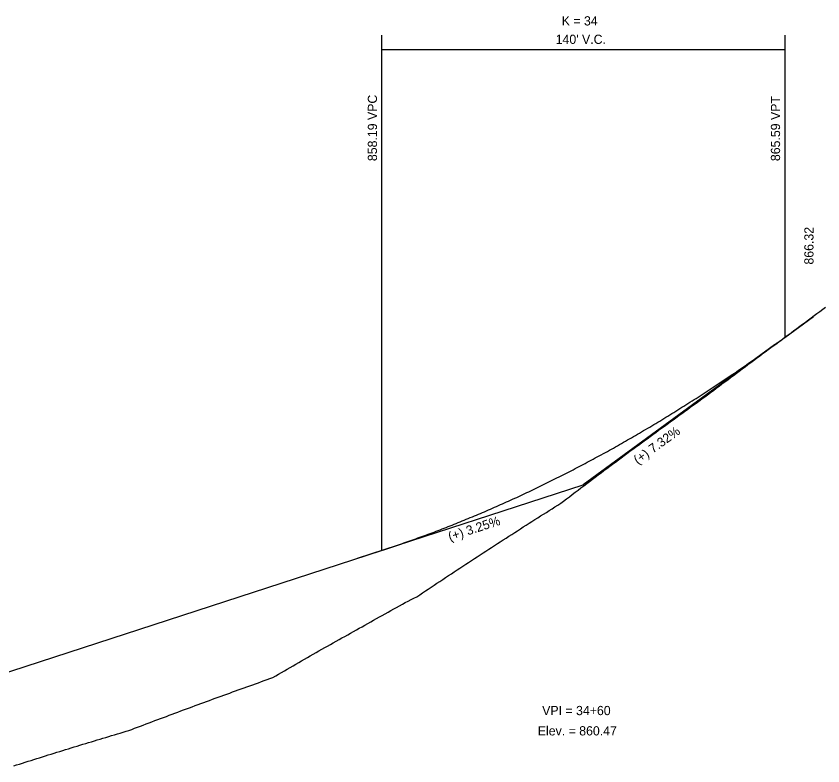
# Model space of a CAD drawing. Extents: x 1738393 to 1742179, y 1214897 to 1219897.
# Drawn here: x 1740142.4 to 1740422.6, y 1217903.8 to 1218164.3 of the extents above; entities that cross this region are included whole.
import ezdxf

# ---------------------------------------------------------------- set-up
doc = ezdxf.new("R2010")
doc.units = 0
for name, color, linetype in [('RD_DDB_GradeTX', 7, 'Continuous'), ('RD_DDB_Profile_EX', 7, 'Continuous'), ('RD_DDB_Profile_Lbl', 7, 'Continuous'), ('RD_DDB_Profile_PR', 7, 'Continuous'), ('RD_DDB_StripGrade', 7, 'Continuous'), ('RD_DDB_VCLbl', 7, 'Continuous')]:
    doc.layers.add(name, color=color, linetype=linetype)

msp = doc.modelspace()

# ---------------------------------------------------------------- linework, layer by layer
at = {"layer": 'RD_DDB_GradeTX'}
for p in [(1740405.87, 1218050.08), (1740261.02, 1217975.92)]:
    msp.add_line(p, (1740339.37, 1218001.42), dxfattribs=at)
at = {"layer": 'RD_DDB_Profile_EX'}
for points in [[(1740384.58, 1218034.23), (1740385.58, 1218034.98), (1740386.58, 1218035.73), (1740387.58, 1218036.48), (1740388.58, 1218037.22), (1740389.58, 1218037.97), (1740390.58, 1218038.72), (1740391.58, 1218039.47), (1740392.58, 1218040.21), (1740393.58, 1218040.96), (1740394.58, 1218041.71), (1740395.58, 1218042.45), (1740396.58, 1218043.2), (1740397.58, 1218043.94), (1740398.58, 1218044.69), (1740399.58, 1218045.43), (1740400.58, 1218046.18), (1740401.58, 1218046.92), (1740402.58, 1218047.67), (1740403.58, 1218048.41), (1740404.58, 1218049.16), (1740405.58, 1218049.87), (1740406.58, 1218050.58), (1740407.58, 1218051.32), (1740408.58, 1218052.07), (1740409.58, 1218052.81), (1740410.58, 1218053.55), (1740411.58, 1218054.29), (1740412.58, 1218055.03), (1740413.58, 1218055.78), (1740414.58, 1218056.52), (1740415.58, 1218057.26), (1740416.58, 1218058), (1740417.58, 1218058.74), (1740418.58, 1218059.49), (1740419.58, 1218060.23), (1740420.58, 1218060.97), (1740421.58, 1218061.71), (1740422.58, 1218062.45), (1740423.58, 1218063.19)], [(1740284.58, 1217964.57), (1740285.58, 1217965.24), (1740286.58, 1217965.91), (1740287.58, 1217966.57), (1740288.58, 1217967.24), (1740289.58, 1217967.9), (1740290.58, 1217968.56), (1740291.58, 1217969.23), (1740292.58, 1217969.89), (1740293.58, 1217970.55), (1740294.58, 1217971.21), (1740295.58, 1217971.87), (1740296.58, 1217972.53), (1740297.58, 1217973.18), (1740298.58, 1217973.84), (1740299.58, 1217974.5), (1740300.58, 1217975.15), (1740301.58, 1217975.81), (1740302.58, 1217976.46), (1740303.58, 1217977.11), (1740304.58, 1217977.76), (1740305.58, 1217978.41), (1740306.58, 1217979.06), (1740307.58, 1217979.71), (1740308.58, 1217980.36), (1740309.58, 1217981.01), (1740310.58, 1217981.65), (1740311.58, 1217982.3), (1740312.58, 1217982.94), (1740313.58, 1217983.59), (1740314.58, 1217984.23), (1740315.58, 1217984.87), (1740316.58, 1217985.51), (1740317.58, 1217986.15), (1740318.58, 1217986.79), (1740319.58, 1217987.43), (1740320.58, 1217988.07), (1740321.58, 1217988.71), (1740322.58, 1217989.35), (1740323.58, 1217989.98), (1740324.58, 1217990.62), (1740325.58, 1217991.25), (1740326.58, 1217991.88), (1740327.58, 1217992.51), (1740328.58, 1217993.15), (1740329.58, 1217993.78), (1740330.58, 1217994.4), (1740331.58, 1217995.03), (1740332.58, 1217995.79), (1740333.58, 1217996.56), (1740334.58, 1217997.32), (1740335.58, 1217998.08), (1740336.58, 1217998.84), (1740337.58, 1217999.59), (1740338.58, 1218000.35), (1740339.58, 1218001.11), (1740340.58, 1218001.87), (1740341.58, 1218002.62), (1740342.58, 1218003.37), (1740343.58, 1218004.13), (1740344.58, 1218004.88), (1740345.58, 1218005.63), (1740346.58, 1218006.38), (1740347.58, 1218007.13), (1740348.58, 1218007.88), (1740349.58, 1218008.63), (1740350.58, 1218009.37), (1740351.58, 1218010.12), (1740352.58, 1218010.87), (1740353.58, 1218011.61), (1740354.58, 1218012.35), (1740355.58, 1218013.08), (1740356.58, 1218013.81), (1740357.58, 1218014.54), (1740358.58, 1218015.27), (1740359.58, 1218016.01), (1740360.58, 1218016.74), (1740361.58, 1218017.47), (1740362.58, 1218018.2), (1740363.58, 1218018.93), (1740364.58, 1218019.66), (1740365.58, 1218020.39), (1740366.58, 1218021.12), (1740367.58, 1218021.85), (1740368.58, 1218022.57), (1740369.58, 1218023.3), (1740370.58, 1218024.03), (1740371.58, 1218024.76), (1740372.58, 1218025.48), (1740373.58, 1218026.21), (1740374.58, 1218026.94), (1740375.58, 1218027.66), (1740376.58, 1218028.39), (1740377.58, 1218029.11), (1740378.58, 1218029.84), (1740379.58, 1218030.56), (1740380.58, 1218031.28), (1740381.58, 1218031.99), (1740382.58, 1218032.74), (1740383.58, 1218033.49), (1740384.58, 1218034.23)], [(1740184.58, 1217917.24), (1740185.58, 1217917.61), (1740186.58, 1217917.99), (1740187.58, 1217918.37), (1740188.58, 1217918.75), (1740189.58, 1217919.12), (1740190.58, 1217919.5), (1740191.58, 1217919.87), (1740192.58, 1217920.25), (1740193.58, 1217920.62), (1740194.58, 1217921), (1740195.58, 1217921.37), (1740196.58, 1217921.74), (1740197.58, 1217922.12), (1740198.58, 1217922.49), (1740199.58, 1217922.86), (1740200.58, 1217923.23), (1740201.58, 1217923.6), (1740202.58, 1217923.97), (1740203.58, 1217924.34), (1740204.58, 1217924.71), (1740205.58, 1217925.07), (1740206.58, 1217925.44), (1740207.58, 1217925.82), (1740208.58, 1217926.18), (1740209.58, 1217926.55), (1740210.58, 1217926.92), (1740211.58, 1217927.28), (1740212.58, 1217927.65), (1740213.58, 1217928.01), (1740214.58, 1217928.37), (1740215.58, 1217928.74), (1740216.58, 1217929.1), (1740217.58, 1217929.46), (1740218.58, 1217929.82), (1740219.58, 1217930.19), (1740220.58, 1217930.55), (1740221.58, 1217930.91), (1740222.58, 1217931.27), (1740223.58, 1217931.63), (1740224.58, 1217931.98), (1740225.58, 1217932.34), (1740226.58, 1217932.7), (1740227.58, 1217933.06), (1740228.58, 1217933.41), (1740229.58, 1217933.77), (1740230.58, 1217934.13), (1740231.58, 1217934.5), (1740232.58, 1217935.07), (1740233.58, 1217935.65), (1740234.58, 1217936.23), (1740235.58, 1217936.81), (1740236.58, 1217937.39), (1740237.58, 1217937.97), (1740238.58, 1217938.55), (1740239.58, 1217939.12), (1740240.58, 1217939.7), (1740241.58, 1217940.28), (1740242.58, 1217940.85), (1740243.58, 1217941.43), (1740244.58, 1217942), (1740245.58, 1217942.57), (1740246.58, 1217943.15), (1740247.58, 1217943.72), (1740248.58, 1217944.29), (1740249.58, 1217944.87), (1740250.58, 1217945.44), (1740251.58, 1217946.01), (1740252.58, 1217946.58), (1740253.58, 1217947.15), (1740254.58, 1217947.72), (1740255.58, 1217948.25), (1740256.58, 1217948.77), (1740257.58, 1217949.33), (1740258.58, 1217949.89), (1740259.58, 1217950.46), (1740260.58, 1217951.02), (1740261.58, 1217951.59), (1740262.58, 1217952.15), (1740263.58, 1217952.71), (1740264.58, 1217953.27), (1740265.58, 1217953.84), (1740266.58, 1217954.4), (1740267.58, 1217954.96), (1740268.58, 1217955.52), (1740269.58, 1217956.07), (1740270.58, 1217956.63), (1740271.58, 1217957.19), (1740272.58, 1217957.74), (1740273.58, 1217958.3), (1740274.58, 1217958.86), (1740275.58, 1217959.41), (1740276.58, 1217959.96), (1740277.58, 1217960.52), (1740278.58, 1217961.07), (1740279.58, 1217961.57), (1740280.58, 1217962.07), (1740281.58, 1217962.57), (1740282.58, 1217963.23), (1740283.58, 1217963.9), (1740284.58, 1217964.57)], [(1740141.58, 1217903.79), (1740142.58, 1217904.11), (1740143.58, 1217904.43), (1740144.58, 1217904.74), (1740145.58, 1217905.06), (1740146.58, 1217905.37), (1740147.58, 1217905.69), (1740148.58, 1217906), (1740149.58, 1217906.32), (1740150.58, 1217906.63), (1740151.58, 1217906.94), (1740152.58, 1217907.26), (1740153.58, 1217907.57), (1740154.58, 1217907.88), (1740155.58, 1217908.19), (1740156.58, 1217908.5), (1740157.58, 1217908.81), (1740158.58, 1217909.12), (1740159.58, 1217909.43), (1740160.58, 1217909.74), (1740161.58, 1217910.05), (1740162.58, 1217910.36), (1740163.58, 1217910.67), (1740164.58, 1217910.97), (1740165.58, 1217911.28), (1740166.58, 1217911.58), (1740167.58, 1217911.89), (1740168.58, 1217912.19), (1740169.58, 1217912.49), (1740170.58, 1217912.8), (1740171.58, 1217913.1), (1740172.58, 1217913.4), (1740173.58, 1217913.7), (1740174.58, 1217914), (1740175.58, 1217914.3), (1740176.58, 1217914.6), (1740177.58, 1217914.9), (1740178.58, 1217915.2), (1740179.58, 1217915.5), (1740180.58, 1217915.8), (1740181.58, 1217916.09), (1740182.58, 1217916.47), (1740183.58, 1217916.86), (1740184.58, 1217917.24)]]:
    msp.add_lwpolyline(points, dxfattribs=at)
at = {"layer": 'RD_DDB_Profile_PR'}
for p, q in [((1740409.37, 1218052.65), (1740419.37, 1218059.97)), ((1740134.37, 1217934.71), (1740269.37, 1217978.64))]:
    msp.add_line(p, q, dxfattribs=at)
msp.add_spline([(1740269.37, 1217978.64), (1740272.17, 1217979.56), (1740274.97, 1217980.51), (1740277.77, 1217981.48), (1740280.57, 1217982.47), (1740283.37, 1217983.48), (1740286.17, 1217984.52), (1740288.97, 1217985.58), (1740291.77, 1217986.66), (1740294.57, 1217987.76), (1740297.37, 1217988.89), (1740300.17, 1217990.04), (1740302.97, 1217991.21), (1740305.77, 1217992.41), (1740308.57, 1217993.63), (1740311.37, 1217994.87), (1740314.17, 1217996.13), (1740316.97, 1217997.42), (1740319.77, 1217998.73), (1740322.57, 1218000.06), (1740325.37, 1218001.42), (1740328.17, 1218002.79), (1740330.97, 1218004.19), (1740333.77, 1218005.62), (1740336.57, 1218007.06), (1740339.37, 1218008.53), (1740342.17, 1218010.02), (1740344.97, 1218011.54), (1740347.77, 1218013.07), (1740350.57, 1218014.63), (1740353.37, 1218016.22), (1740356.17, 1218017.82), (1740358.97, 1218019.45), (1740361.77, 1218021.1), (1740364.57, 1218022.77), (1740367.37, 1218024.47), (1740370.17, 1218026.19), (1740372.97, 1218027.93), (1740375.77, 1218029.7), (1740378.57, 1218031.48), (1740381.37, 1218033.29), (1740384.17, 1218035.13), (1740386.97, 1218036.98), (1740389.77, 1218038.86), (1740392.57, 1218040.76), (1740395.37, 1218042.69), (1740398.17, 1218044.63), (1740400.97, 1218046.6), (1740403.77, 1218048.59), (1740406.57, 1218050.61), (1740409.37, 1218052.65)], degree=3, dxfattribs=at)
at = {"layer": 'RD_DDB_VCLbl'}
for p, q in [((1740269.37, 1218157.65), (1740269.37, 1217978.64)), ((1740409.37, 1218157.65), (1740409.37, 1218052.65)), ((1740269.37, 1218152.65), (1740409.37, 1218152.65))]:
    msp.add_line(p, q, dxfattribs=at)

# ---------------------------------------------------------------- texts
at = {"layer": 'RD_DDB_GradeTX'}
for s, rotation, p in [('(+) 7.32%', 36.1976, (1740358.34, 1218008.38)), ('(+) 3.25%', 18.0262, (1740293.09, 1217981.84))]:
    msp.add_text(s, height=3.2, rotation=rotation, dxfattribs=at).set_placement(p)
at = {"layer": 'RD_DDB_Profile_Lbl'}
msp.add_text('866.32', height=3.2, rotation=90, dxfattribs=at).set_placement((1740419.37, 1218077.97))
for s, p in [('VPI = 34+60', (1740325.12, 1217921.42)), ('Elev. = 860.47', (1740323.6, 1217914.37))]:
    msp.add_text(s, height=3.2, dxfattribs=at).set_placement(p)
at = {"layer": 'RD_DDB_StripGrade'}
for s, p in [('858.19 VPC', (1740267.76, 1218113.92)), ('865.59 VPT', (1740407.76, 1218113.92))]:
    msp.add_text(s, height=3.2, rotation=90, dxfattribs=at).set_placement(p)
at = {"layer": 'RD_DDB_VCLbl'}
for s, p in [('K = 34', (1740331.91, 1218161.05)), ("140' V.C.", (1740329.81, 1218154.65))]:
    msp.add_text(s, height=3.2, dxfattribs=at).set_placement(p)

doc.saveas('drawing.dxf')
